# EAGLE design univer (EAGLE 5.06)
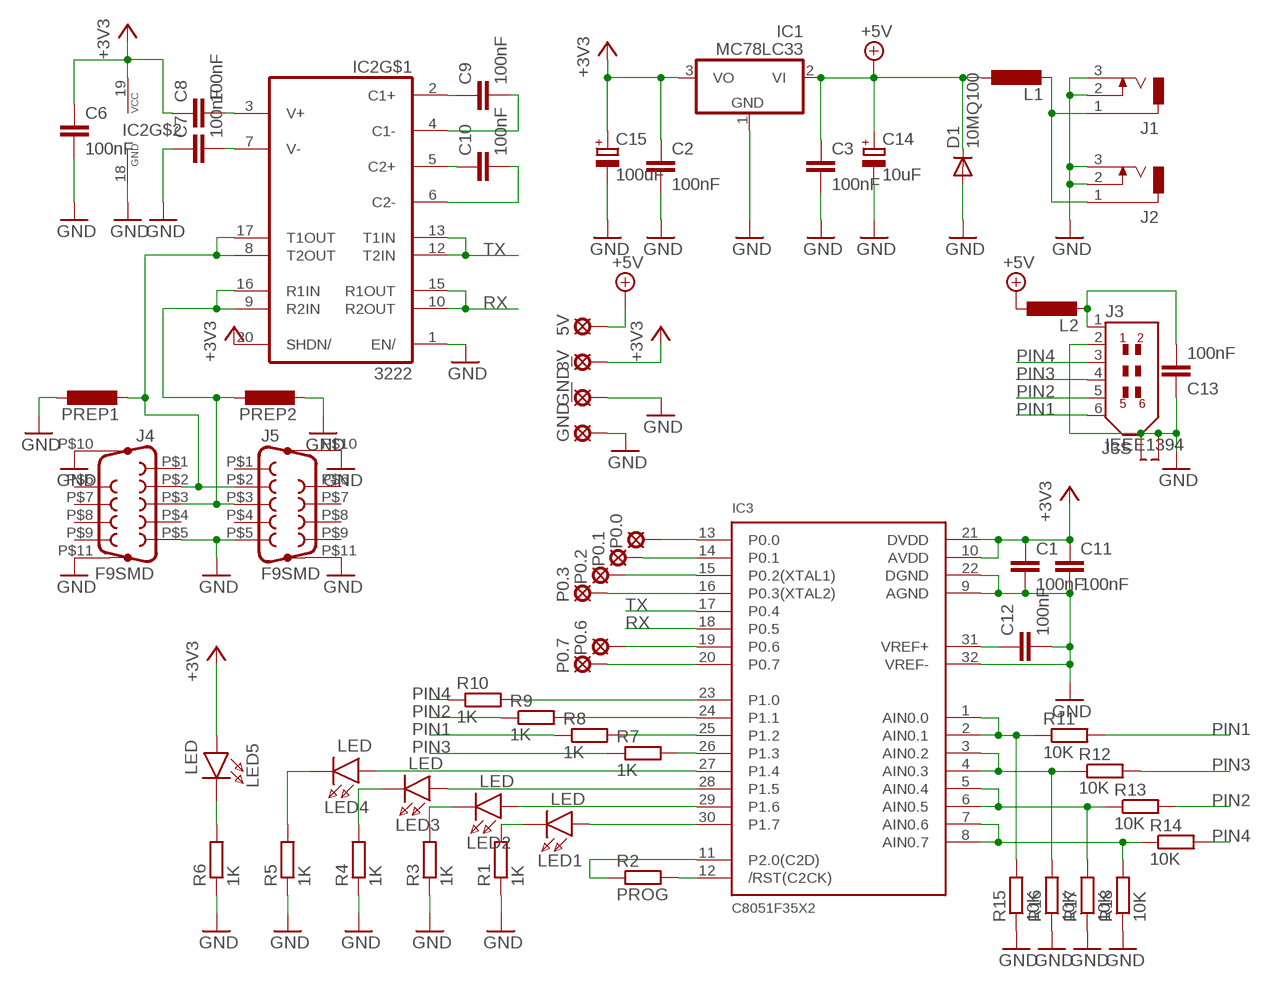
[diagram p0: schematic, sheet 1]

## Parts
3V  LSP10  [LSP10]
5V  LSP10  [LSP10]
C1  100nF  C0805  [0805]
C2  100nF  C0805  [0805]
C3  100nF  C0805  [0805]
C6  100nF  C0805  [0805]
C7  100nF  C0805  [0805]
C8  100nF  C0805  [0805]
C9  100nF  C0805  [0805]
C10  100nF  C0805  [0805]
C11  100nF  C0805  [0805]
C12  100nF  C0805  [0805]
C13  100nF  C0805  [0805]
C14  10uF  CPOL-EUSMCB  [SMC_B]
C15  100uF  CPOL-EUSMCB  [SMC_B]
D1  10MQ100  CGRM4001-G  [SOD-123_MINI-SMA]
GND_  LSP10  [LSP10]
GND__  LSP10  [LSP10]
IC1  MC78LC33  MC78LC00  [SOT23-5]
IC2  3222  [SSOP20]
IC3  C8051F35X2  [LQFP32]
J1  DCJ0303  [DCJ0303]
J2  DCJ0303  [DCJ0303]
J3  IEEE1394  IEEE1394_6P-85-32007-10X-1  [85-32007-10X-1]
J4  F9SMD  [F09SMD]
J5  F9SMD  [F09SMD]
L1  L0805  [0805]
L2  L0805  [0805]
LED1  LED  [0805]
LED2  LED  [0805]
LED3  LED  [0805]
LED4  LED  [0805]
LED5  LED  [0805]
P0.0  LSP10  [LSP10]
P0.1  LSP10  [LSP10]
P0.2  LSP10  [LSP10]
P0.3  LSP10  [LSP10]
P0.6  LSP10  [LSP10]
P0.7  LSP10  [LSP10]
PREP1  L0805  [0805]
PREP2  L0805  [0805]
R1  1K  R0805  [0805]
R2  PROG  R0805  [0805]
R3  1K  R0805  [0805]
R4  1K  R0805  [0805]
R5  1K  R0805  [0805]
R6  1K  R0805  [0805]
R7  1K  R0805  [0805]
R8  1K  R0805  [0805]
R9  1K  R0805  [0805]
R10  1K  R0805  [0805]
R11  10K  R0805  [0805]
R12  10K  R0805  [0805]
R13  10K  R0805  [0805]
R14  10K  R0805  [0805]
R15  10K  R0805  [0805]
R16  10K  R0805  [0805]
R17  10K  R0805  [0805]
R18  10K  R0805  [0805]

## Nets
+3V3: 3V.MP C1.P$1 C2.P$1 C6.P$1 C8.P$1 C11.P$1 C15.+ IC1.3(VO) IC2.19(VCC) IC2.20(SHDN/) IC3.10(AVDD) IC3.21(DVDD) LED5.P$1(A)
+5V: 5V.MP C3.P$1 C14.+ D1.C IC1.2(VI) L1.P$1 L2.P$1
GND: C1.P$2 C2.P$2 C3.P$2 C6.P$2 C7.P$1 C11.P$2 C12.P$2 C13.P$1 C14.- C15.- D1.A GND_.MP GND__.MP IC1.1(GND) IC2.1(EN/) IC2.18(GND) IC3.9(AGND) IC3.22(DGND) IC3.32(VREF-) J1.2 J1.3 J2.2 J2.3 J3.2 J3.M1(S1) J3.M2(S2) J4.P$5 J4.P$10(G1) J4.P$11(G2) J5.P$5 J5.P$10(G1) J5.P$11(G2) PREP1.P$1 PREP2.P$2 R1.P$1 R3.P$1 R4.P$1 R5.P$1 R6.P$1 R15.P$1 R16.P$1 R17.P$1 R18.P$1
N$1: IC3.11(P2.0(C2D)) R2.P$1
N$2: J1.1 J2.1 L1.P$2
N$3: IC2.8(T2OUT) IC2.17(T1OUT) J4.P$2 J5.P$2 PREP1.P$2
N$4: IC2.9(R2IN) IC2.16(R1IN) J4.P$3 J5.P$3 PREP2.P$1
N$5: IC3.12(/RST(C2CK)) R2.P$2
N$6: C10.P$2 IC2.6(C2-)
N$7: C10.P$1 IC2.5(C2+)
N$8: C8.P$2 IC2.3(V+)
N$9: C7.P$2 IC2.7(V-)
N$10: C9.P$2 IC2.4(C1-)
N$11: C9.P$1 IC2.2(C1+)
N$12: C12.P$1 IC3.31(VREF+)
N$13: IC3.13(P0.0) P0.0.MP
N$14: IC3.14(P0.1) P0.1.MP
N$15: IC3.15(P0.2(XTAL1)) P0.2.MP
N$16: IC3.16(P0.3(XTAL2)) P0.3.MP
N$17: IC3.19(P0.6) P0.6.MP
N$18: IC3.20(P0.7) P0.7.MP
N$19: LED5.P$2(K) R6.P$2
N$20: IC3.30(P1.7) LED1.P$1(A)
N$21: IC3.29(P1.6) LED2.P$1(A)
N$22: IC3.28(P1.5) LED3.P$1(A)
N$23: IC3.27(P1.4) LED4.P$1(A)
N$24: LED4.P$2(K) R5.P$2
N$25: LED3.P$2(K) R4.P$2
N$26: LED2.P$2(K) R3.P$2
N$27: LED1.P$2(K) R1.P$2
N$29: C13.P$2 J3.1 L2.P$2
N$30: IC3.26(P1.3) R7.P$2
N$32: IC3.1(AIN0.0) IC3.2(AIN0.1) R11.P$1 R15.P$2
N$33: IC3.3(AIN0.2) IC3.4(AIN0.3) R12.P$1 R16.P$2
N$34: IC3.5(AIN0.4) IC3.6(AIN0.5) R13.P$1 R17.P$2
N$35: IC3.7(AIN0.6) IC3.8(AIN0.7) R14.P$1 R18.P$2
PIN1: J3.6 R8.P$1 R11.P$2
PIN2: J3.5 R9.P$1 R13.P$2
PIN3: J3.4 R7.P$1 R12.P$2
PIN4: J3.3 R10.P$1 R14.P$2
PIN_1: IC3.23(P1.0) R10.P$2
PIN_2: IC3.24(P1.1) R9.P$2
PIN_3: IC3.25(P1.2) R8.P$2
RX: IC2.10(R2OUT) IC2.15(R1OUT) IC3.18(P0.5)
TX: IC2.12(T2IN) IC2.13(T1IN) IC3.17(P0.4)
Unconnected: J4.P$1 J4.P$4 J4.P$6 J4.P$7 J4.P$8 J4.P$9 J5.P$1 J5.P$4 J5.P$6 J5.P$7 J5.P$8 J5.P$9

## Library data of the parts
3V 5V GND_ GND__ P0.0 P0.1-P0.3 P0.6 P0.7 = solpad:LSP10: SOLDER PAD
C1-C3 C6-C13 = vyskomer2:C0805
C14 C15 = rcl:CPOL-EU: POLARIZED CAPACITOR, European symbol
D1 = diode:CGRM400*-G: Molded plasitc,JEDEC SOD-123/Mini SMA
IC1 = vyskomer2:MC78LC00
IC2 = !moje:3222
IC3 = silabs:C8051F35X2
J1 J2 = con-jack:DCJ0303: DC POWER JACK Source: DCJ0303.pdf
J3 = con-cypressindustries:IEEE1394_6P-: IEEE1394 6P Firewire Receptacle Source: www.cypressindustries.com
J4 J5 = con-subd:F9SMD
L1 L2 PREP1 PREP2 = vyskomer2:L0805
LED1-LED5 = vyskomer2:LED
R1-R18 = vyskomer2:R0805

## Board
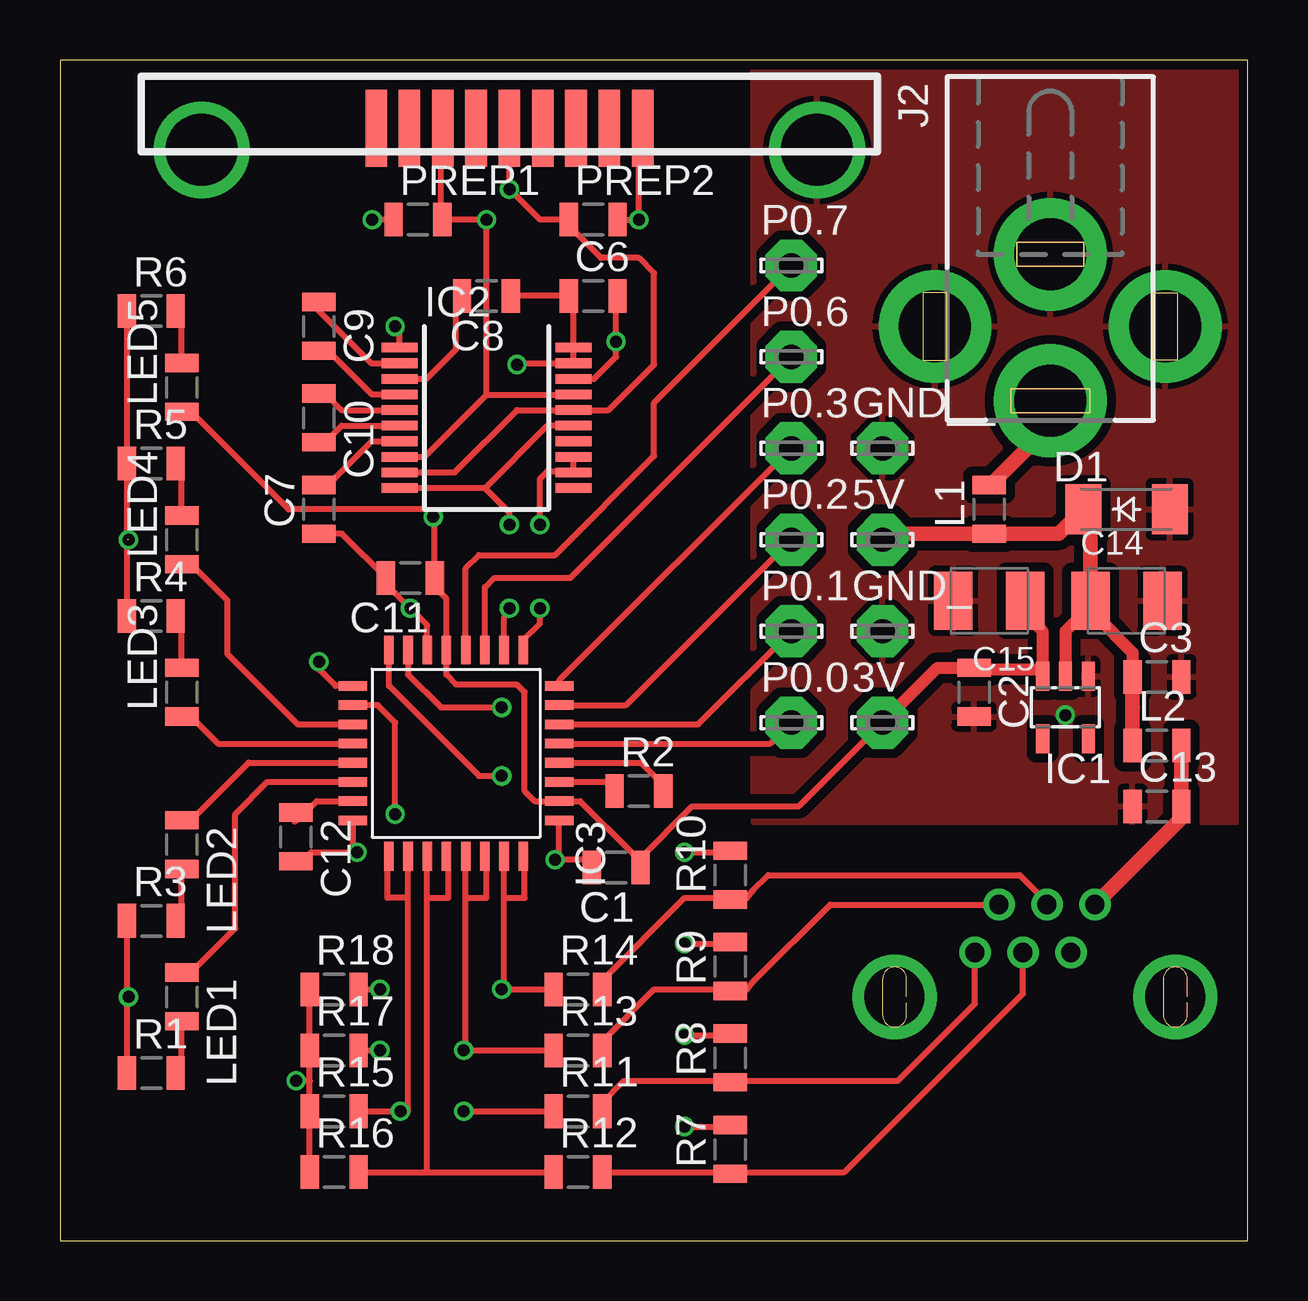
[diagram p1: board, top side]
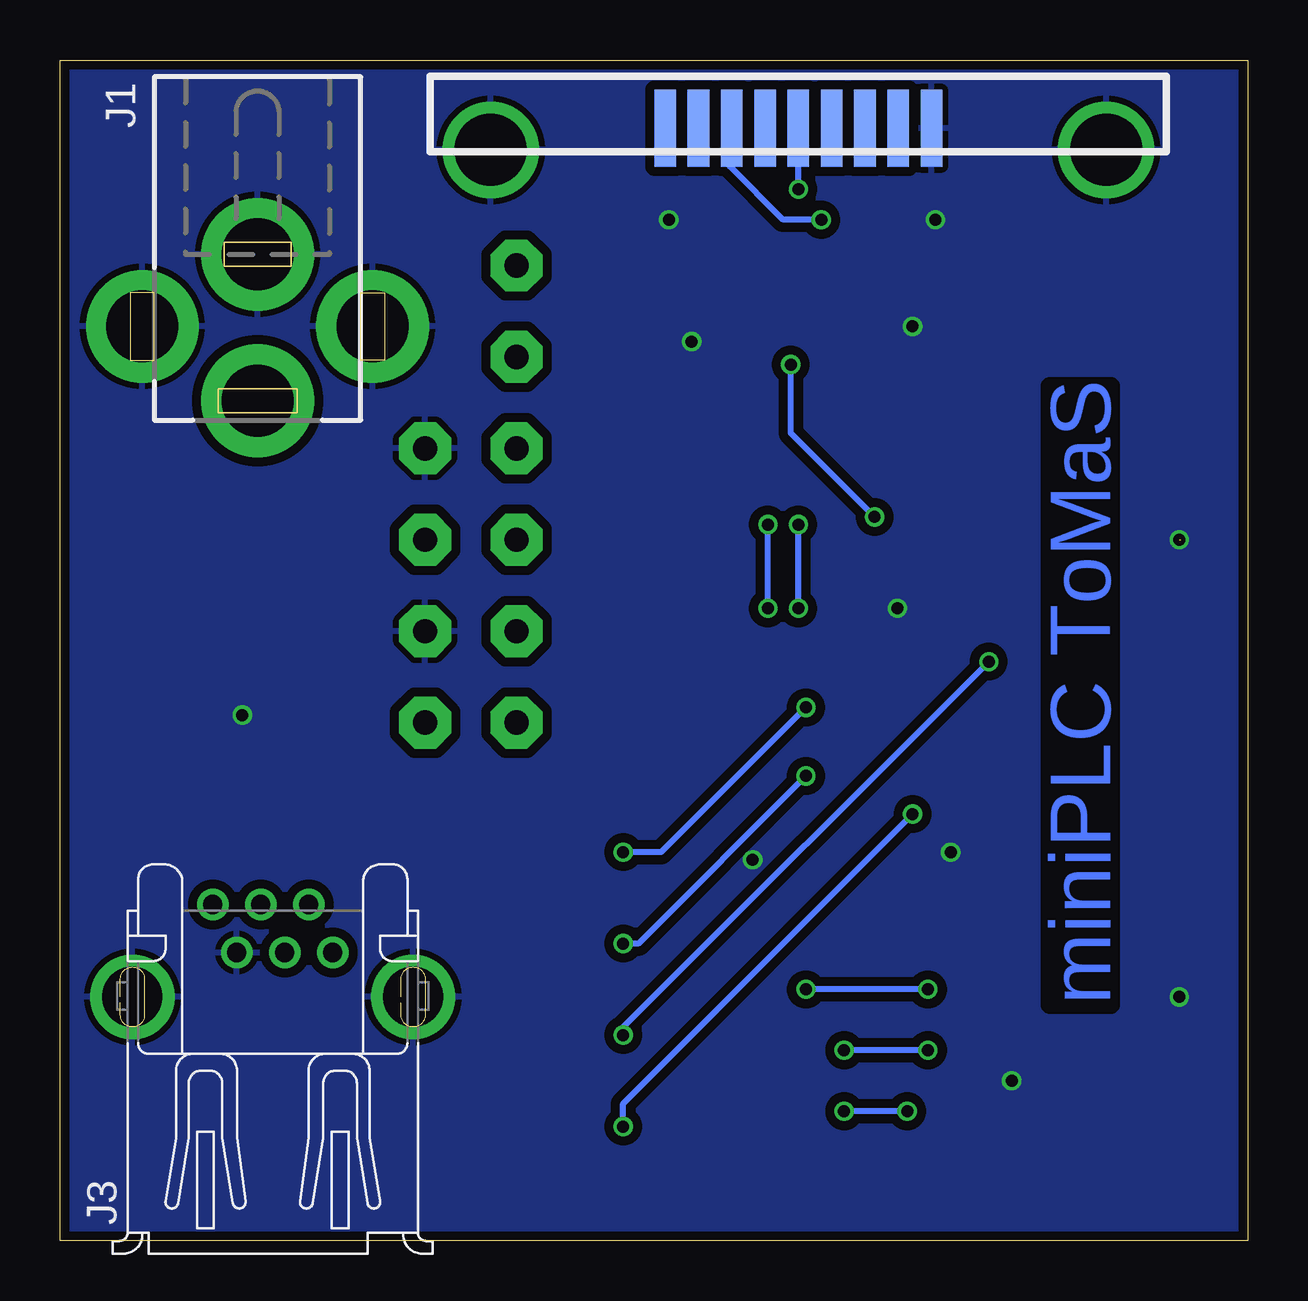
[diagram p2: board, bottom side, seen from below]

Size 49.51 x 49.2 mm. Coordinates in mm from the lower left corner, seen from the top.
Outline: 0,0 49.51,0 49.51,49.2 0,49.2 0,0
Copper layers (1*16): Top 0.035mm / dielectric 1.5mm / Bottom 0.035mm
Design rules "Fusion_eagle_rule_v1.1": minimum track width 6mil, minimum drill 12mil, track to track 6mil, track to pad 6mil, pad to pad 6mil, via to via 6mil, smd to smd 0mil, copper to edge 10mil, drill to drill 10mil, minimum pad ring 10mil, minimum via ring 6mil, stop-mask expansion 2mil, vias tented up to drill 100mil, thermal gap 10mil

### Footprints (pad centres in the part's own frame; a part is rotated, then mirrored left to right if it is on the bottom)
LSP10 = drill 1.016 pad 2.159 octagon: MP 0,0
0805 = smd 0.762 x 1.397: P$1 -1.016,0; P$2 1.016,0
SMC_B = smd 1.6 x 2.4: + -1.5,0; - 1.5,0
SOD-123_MINI-SMA = smd 1.5 x 2.1: A 1.8,0; C -1.8,0
SOT23-5 = smd 0.55 x 1.2: 1 -0.95,-1.3; 2 0,-1.3; 3 0.95,-1.3; 4 0.95,1.3; 5 -0.95,1.3
SSOP20 = smd 1.5 x 0.4: 1 -3.625,2.925; 2 -3.625,2.275; 3 -3.625,1.625; 4 -3.625,0.975; 5 -3.625,0.325; 6 -3.625,-0.325; 7 -3.625,-0.975; 8 -3.625,-1.625; 9 -3.625,-2.275; 10 -3.625,-2.925; 11 3.625,-2.925; 12 3.625,-2.275; 13 3.625,-1.625; 14 3.625,-0.975; 15 3.625,-0.325; 16 3.625,0.325; 17 3.625,0.975; 18 3.625,1.625; 19 3.625,2.275; 20 3.625,2.925
LQFP32 = smd 1.2 x 0.4: 1 -4.3,2.8; 2 -4.3,2; 3 -4.3,1.2; 4 -4.3,0.4; 5 -4.3,-0.4; 6 -4.3,-1.2; 7 -4.3,-2; 8 -4.3,-2.8; 17 4.3,-2.8; 18 4.3,-2; 19 4.3,-1.2; 20 4.3,-0.4; 21 4.3,0.4; 22 4.3,1.2; 23 4.3,2; 24 4.3,2.8 | smd 0.4 x 1.2: 9 -2.8,-4.3; 10 -2,-4.3; 11 -1.2,-4.3; 12 -0.4,-4.3; 13 0.4,-4.3; 14 1.2,-4.3; 15 2,-4.3; 16 2.8,-4.3; 25 2.8,4.3; 26 2,4.3; 27 1.2,4.3; 28 0.4,4.3; 29 -0.4,4.3; 30 -1.2,4.3; 31 -2,4.3; 32 -2.8,4.3
DCJ0303 = drill 3 pad 4.7 round: 1 0,3.1; 2 4.8,0; 3 0,-3
85-32007-10X-1 = drill 0.8 pad 1.27 round: 1 -2.5,3.85; 2 -1.5,1.85; 3 -0.5,3.85; 4 0.5,1.85; 5 1.5,3.85; 6 2.5,1.85 | drill 2.5 round: M1 -5.85,0; M2 5.85,0
F09SMD = smd 0.9 x 3.2: P$1 -5.552,0; P$2 -2.776,0; P$3 0,0; P$4 2.776,0; P$5 5.552,0; P$6 -4.164,0; P$7 -1.388,0; P$8 1.388,0; P$9 4.164,0 | drill 3 round: P$10 -12.827,-0.9; P$11 12.827,-0.9

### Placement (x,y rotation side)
3V  34.29,21.59 0 top
5V  34.29,29.21 0 top
C1  23.18,15.56 180 top
C2  38.1,22.86 270 top
C3  45.72,23.5 0 top
C6  22.23,39.37 0 top
C7  10.79,30.48 90 top
C8  17.78,39.37 180 top
C9  10.79,38.1 270 top
C10  10.79,34.29 270 top
C11  14.61,27.62 180 top
C12  9.84,16.83 270 top
C13  45.72,18.1 0 top
C14  44.45,26.67 0 top
C15  38.73,26.67 180 top
D1  44.45,30.48 0 top
GND_  34.29,25.4 0 top
GND__  34.29,33.02 0 top
IC1  41.91,22.23 180 top
IC2  17.78,34.29 0 top
IC3  16.51,20.32 90 top
J1  41.27,38.1 180 bottom
J2  41.27,38.1 180 top
J3  40.64,10.16 0 bottom
J4  18.73,46.35 0 top
J5  18.73,46.35 0 bottom
L1  38.73,30.48 90 top
L2  45.72,20.64 0 top
LED1  5.08,10.16 270 top
LED2  5.08,16.51 270 top
LED3  5.08,22.86 90 top
LED4  5.08,29.21 90 top
LED5  5.08,35.56 90 top
P0.0  30.48,21.59 0 top
P0.1  30.48,25.4 0 top
P0.2  30.48,29.21 0 top
P0.3  30.48,33.02 0 top
P0.6  30.48,36.83 0 top
P0.7  30.48,40.64 0 top
PREP1  14.92,42.55 0 top
PREP2  22.23,42.55 0 top
R1  3.81,6.99 0 top
R2  24.13,18.73 0 top
R3  3.81,13.34 0 top
R4  3.81,26.04 0 top
R5  3.81,32.38 0 top
R6  3.81,38.73 0 top
R7  27.94,3.81 90 top
R8  27.94,7.62 90 top
R9  27.94,11.43 90 top
R10  27.94,15.24 90 top
R11  21.59,5.4 0 top
R12  21.59,2.86 0 top
R13  21.59,7.94 0 top
R14  21.59,10.48 0 top
R15  11.43,5.4 0 top
R16  11.43,2.86 0 top
R17  11.43,7.94 0 top
R18  11.43,10.48 0 top

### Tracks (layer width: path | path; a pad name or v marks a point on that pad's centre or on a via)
+3V3  (via drill 0.5)
  Top 0.254: 3V.MP 30.8,18.1 26.35,18.1 24.13,15.88 24.45,15.49 C1.P$1 | C1.P$1 24.13,15.49 | LED5.P$1 5.33,34.29 5.71,34.29 9.53,30.48 15.24,30.48 v15.56,30.16 15.62,30.1 C11.P$1 15.88,27.37 15.88,26.99 16.11,26.75 IC3.21 16.11,23.58 16.51,23.18 19.05,23.18 19.37,22.86 19.37,18.73 19.78,18.32 IC3.10 21.68,18.32 23.81,16.19 24.13,15.62 C1.P$1 | C8.P$1 C6.P$1 21.41,39.17 IC2.20 IC2.19 19.1,36.56 v19.05,36.51
  Top 0.508: C15.+ 40.32,26.58 40.32,26.04 40.96,25.4 IC1.3 40.96,23.81 38.16,23.81 C2.P$1 36.58,23.88 3V.MP
  Bottom 0.254: v19.05,36.51 19.05,33.66 v15.56,30.16
+5V
  Top 0.508: IC1.2 41.91,25.4 42.23,25.72 42.86,25.72 43.18,26.04 | 43.18,26.04 43.18,26.44 C14.+ | 44.77,22.23 44.7,22.29 C3.P$1 44.7,24.51 43.18,26.04
  Top 0.61: C3.P$1 L2.P$1 | 5V.MP 34.54,29.46 L1.P$1 41.63,29.46 D1.C 42.95,30.18 C14.+
GND  (via drill 0.5)  (1 unrouted)
  Top 0.254: R1.P$1 2.79,10.16 | 2.79,10.16 R3.P$1 | R4.P$1 2.79,29.21 R5.P$1 R6.P$1 | 2.79,10.16 v2.86,10.16 | R18.P$1 R17.P$1 10.41,6.67 | R16.P$1 R15.P$1 10.41,6.67 | 10.41,6.67 v9.84,6.67 | IC3.32 12.21,16.19 v12.38,16.19 10.48,16.19 10.1,15.81 C12.P$2 | IC3.9 20.81,16.05 v20.64,15.88 21.91,15.88 22.16,15.3 C1.P$2 | IC3.22 15.31,25.65 v14.61,26.35 13.97,26.99 13.65,27.24 C11.P$2 11.75,29.46 C7.P$1 | IC2.18 22.26,35.91 23.18,36.83 v23.18,37.47 23.18,39.31 C6.P$2 | IC2.1 14.15,37.97 v13.97,38.1 | PREP1.P$1 v13.02,42.55 | PREP2.P$2 v24.13,42.55 24.13,46.04 24.29,46.2 J4.P$5
  other vias: 2.86,29.21 41.91,21.91
  pour Bottom (isolate 0.381): 0,49.53 49.53,49.53 49.53,0 0,0
  pour Top (isolate 0.381): 49.53,48.9 28.89,48.9 28.89,17.46 49.53,17.46
N$1
  Top 0.254: IC3.11 23.04,19.12 R2.P$1
N$2
  Top 0.61: L1.P$2 38.8,31.5 40.96,33.66 J1.1
N$3  (via drill 0.5)
  Top 0.254: IC2.8 15.2,32.66 17.78,35.24 | 17.78,35.24 21.38,35.24 IC2.17 | J4.P$2 15.94,46.34 15.88,44.45 15.88,42.86 PREP1.P$2 v17.78,42.55 17.78,35.24
  Bottom 0.254: v17.78,42.55 19.37,42.55 21.59,44.77 21.59,46.27 J5.P$2
N$4  (via drill 0.5)
  Top 0.254: IC2.9 16.46,32.02 19.05,34.61 21.4,34.61 IC2.16 22.87,34.62 24.77,36.51 24.77,40.32 24.13,40.96 22.54,40.96 21.59,41.91 21.27,42.16 PREP2.P$1 20,42.55 v18.73,43.81 J4.P$3
  Bottom 0.254: v18.73,43.81 J4.P$3
N$5
  Top 0.254: IC3.12 24.21,19.92 24.77,19.37 25.08,19.11 R2.P$2
N$6
  Top 0.254: IC2.6 11.74,33.97 11.11,33.34 10.86,33.34 C10.P$2
N$7
  Top 0.254: IC2.5 11.74,34.62 11.11,35.24 11.05,35.24 C10.P$1
N$8
  Top 0.254: IC2.3 15.28,35.91 16.51,37.15 16.51,39.12 C8.P$2
N$9
  Top 0.254: IC2.7 12.99,33.31 11.43,31.75 11.05,31.43 C7.P$2
N$10
  Top 0.254: IC2.4 12.99,35.27 11.43,36.83 11.05,36.83 C9.P$2
N$11
  Top 0.254: IC2.2 12.96,36.56 10.79,38.73 10.86,39.37 C9.P$1
N$12
  Top 0.254: IC3.31 10.7,18.32 10.16,17.78 9.78,17.46 C12.P$1
N$13
  Top 0.254: IC3.13 29.61,20.72 P0.0.MP
N$14
  Top 0.254: IC3.14 26.6,21.52 P0.1.MP
N$15
  Top 0.254: IC3.15 23.59,22.32 P0.2.MP
N$16
  Top 0.254: IC3.16 20.81,23.35 P0.3.MP
N$17
  Top 0.254: IC3.19 17.71,27.23 18.1,27.62 21.27,27.62 P0.6.MP
N$18
  Top 0.254: IC3.20 16.91,28.02 17.46,28.57 20.64,28.57 24.77,32.7 24.77,34.92 P0.7.MP
N$19
  Top 0.254: LED5.P$2 5.08,38.48 R6.P$2
N$20
  Top 0.254: IC3.30 8.64,19.12 7.3,17.78 7.3,13.02 5.71,11.43 5.33,11.43 LED1.P$1
N$21
  Top 0.254: IC3.29 7.86,19.92 5.71,17.78 5.33,17.78 LED2.P$1
N$22
  Top 0.254: IC3.28 6.58,20.72 5.71,21.59 5.33,21.59 LED3.P$1
N$23
  Top 0.254: IC3.27 9.91,21.52 6.99,24.45 6.99,26.67 5.71,27.94 5.33,27.94 LED4.P$1
N$24
  Top 0.254: LED4.P$2 5.08,32.13 R5.P$2
N$25
  Top 0.254: R4.P$2 4.83,25.65 5.08,25.4 LED3.P$2
N$26
  Top 0.254: R3.P$2 4.83,13.72 5.08,13.97 LED2.P$2
N$27
  Top 0.254: R1.P$2 4.83,7.37 5.08,7.62 LED1.P$2
N$29
  Top 0.61: J3.1 46.74,17.61 C13.P$2 L2.P$2
N$30  (via drill 0.5)
  Top 0.254: v26.04,4.76 28.19,4.76 R7.P$2 | IC3.26 13.24,22.32 13.97,21.59 v13.97,17.78
  Bottom 0.254: v26.04,4.76 26.04,5.71 v13.97,17.78
N$32  (via drill 0.5)
  Top 0.254: R15.P$2 v14.19,5.4 14.51,5.4 14.51,14.29 | v16.83,5.4 R11.P$1 | 14.51,14.29 IC3.2 | IC3.1 13.65,16.02 13.65,14.29 14.51,14.29
  Bottom 0.254: v14.19,5.4 v16.83,5.4
N$33
  Top 0.254: R16.P$2 15.24,2.86 | 15.24,2.86 R12.P$1 | 15.31,14.29 15.31,2.93 15.24,2.86 | 15.31,14.29 IC3.3 | IC3.4 16.19,16.02 16.19,14.29 15.31,14.29
N$34  (via drill 0.5)
  Top 0.254: 16.91,7.94 R13.P$1 | 16.91,7.94 16.91,14.29 | 16.91,14.29 IC3.5 | R17.P$2 v13.34,7.94 | v16.83,7.94 16.91,7.94 | IC3.6 17.78,16.02 17.78,14.29 16.91,14.29
  Bottom 0.254: v13.34,7.94 v16.83,7.94
N$35  (via drill 0.5)
  Top 0.254: 18.51,10.48 R14.P$1 | 18.51,10.48 18.51,14.29 | 18.51,14.29 IC3.7 | R18.P$2 v13.34,10.48 | v18.41,10.48 18.51,10.48 | IC3.8 19.37,16.02 19.37,14.29 18.51,14.29
  Bottom 0.254: v13.34,10.48 v18.41,10.48
PIN1
  Top 0.254: R11.P$2 22.54,5.71 23.5,6.67 28,6.67 R8.P$1 28.32,6.67 34.92,6.67 38.14,9.88 J3.6
PIN2
  Top 0.254: R13.P$2 22.54,8.26 24.77,10.48 28.32,10.48 R9.P$1 28.64,10.48 28.89,10.79 32.11,14.01 J3.5
PIN3
  Top 0.254: R12.P$2 28,2.86 R7.P$1 28.32,2.86 32.7,2.86 40.14,10.29 J3.4
PIN4
  Top 0.254: R14.P$2 22.54,10.79 26.04,14.29 28.32,14.29 R10.P$1 28.64,14.29 28.89,14.61 29.53,15.24 40.01,15.24 41.23,14.01 J3.3
PIN_1  (via drill 0.5)
  Top 0.254: v26.04,16.19 28.19,16.19 R10.P$2 | IC3.23 14.51,23.59 15.88,22.23 v18.41,22.23
  Bottom 0.254: v26.04,16.19 24.45,16.19 v18.41,22.23
PIN_2  (via drill 0.5)
  Top 0.254: v26.04,12.38 28.19,12.38 R9.P$2 | IC3.24 13.71,23.12 17.46,19.37 v18.41,19.37
  Bottom 0.254: v26.04,12.38 25.4,12.38 v18.41,19.37
PIN_3  (via drill 0.5)
  Top 0.254: v26.04,8.57 28.19,8.57 R8.P$2 | IC3.25 11.49,23.12 10.79,23.81 v10.79,24.13
  Bottom 0.254: v26.04,8.57 26.04,8.89 v10.79,24.13
RX  (via drill 0.5)
  Top 0.254: 17.71,31.36 IC2.10 | 17.71,31.36 20.32,33.97 21.4,33.97 IC2.15 | IC3.18 18.51,25.94 v18.73,26.35 | v18.73,29.84 18.73,30.34 17.71,31.36
  Bottom 0.254: v18.73,26.35 v18.73,29.84
TX  (via drill 0.5)
  Top 0.254: IC3.17 19.31,25.02 20,25.72 v20,26.35 | v20,29.84 20,31.75 20.32,32.07 21.35,32.07 IC2.12 IC2.13
  Bottom 0.254: v20,26.35 v20,29.84

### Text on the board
Bottom: miniPLC ToMaS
